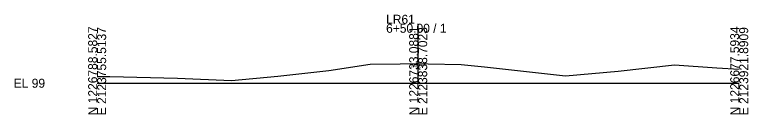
# Model space of a CAD drawing. Extents: x 2126751 to 2128979, y 1225108 to 1234639.
# Drawn here: x 2126750.9 to 2126979.4, y 1231607.5 to 1231638.6 of the extents above; entities that cross this region are included whole.
import ezdxf

# ---------------------------------------------------------------- set-up
doc = ezdxf.new("R2010")
doc.units = 0
for name, color, linetype in [('XS_CELL', 7, 'Continuous'), ('XS_X_GROUND', 7, 'Continuous'), ('XS_X_GROUND_TX', 7, 'Continuous')]:
    doc.layers.add(name, color=color, linetype=linetype)

msp = doc.modelspace()

# ---------------------------------------------------------------- linework, layer by layer
at = {"layer": 'XS_CELL'}
for p, q in [((2126876.61, 1231617.21), (2126876.61, 1231635.74)), ((2126776.61, 1231617.21), (2126876.61, 1231617.21)), ((2126876.61, 1231617.21), (2126976.61, 1231617.21))]:
    msp.add_line(p, q, dxfattribs=at)
at = {"layer": 'XS_X_GROUND'}
for p, q in [((2126848.74, 1231621.21), (2126861.62, 1231623.11)), ((2126861.62, 1231623.11), (2126870.95, 1231623.29)), ((2126870.95, 1231623.29), (2126875.98, 1231623.39)), ((2126875.98, 1231623.39), (2126876.61, 1231623.37)), ((2126876.61, 1231623.37), (2126879.67, 1231623.29)), ((2126879.67, 1231623.29), (2126889.95, 1231623.09)), ((2126889.95, 1231623.09), (2126897.23, 1231622.27)), ((2126897.23, 1231622.27), (2126922.48, 1231619.55)), ((2126938.88, 1231620.94), (2126956.45, 1231622.9)), ((2126956.45, 1231622.9), (2126969.61, 1231622.03)), ((2126969.61, 1231622.03), (2126976.61, 1231621.56)), ((2126776.61, 1231619.35), (2126780.56, 1231619.34)), ((2126780.56, 1231619.34), (2126801.64, 1231618.82)), ((2126818.45, 1231618.04), (2126832.91, 1231619.44)), ((2126832.91, 1231619.44), (2126848.74, 1231621.21)), ((2126922.48, 1231619.55), (2126938.88, 1231620.94)), ((2126801.64, 1231618.82), (2126818.45, 1231618.04))]:
    msp.add_line(p, q, dxfattribs=at)

# ---------------------------------------------------------------- texts
at = {"layer": 'XS_CELL'}
for s, p in [('LR61', (2126866.61, 1231635.74)), ('6+50.00 / 1', (2126866.61, 1231632.94)), ('EL 99', (2126750.61, 1231615.81))]:
    msp.add_text(s, height=2.8, dxfattribs=at).set_placement(p)
for s, p in [('N 1226788.5827', (2126776.61, 1231607.21)), ('E 2123755.5137', (2126779.41, 1231607.21)), ('N 1226733.0881', (2126876.61, 1231607.21)), ('E 2123838.7023', (2126879.41, 1231607.21)), ('N 1226677.5934', (2126976.61, 1231607.21)), ('E 2123921.8909', (2126979.41, 1231607.21))]:
    msp.add_text(s, height=2.8, rotation=90, dxfattribs=at).set_placement(p)
at = {"layer": 'XS_X_GROUND_TX'}
msp.add_text('105.16', height=1, dxfattribs=at).set_placement((2126874.05, 1231622.21))

doc.saveas('drawing.dxf')
